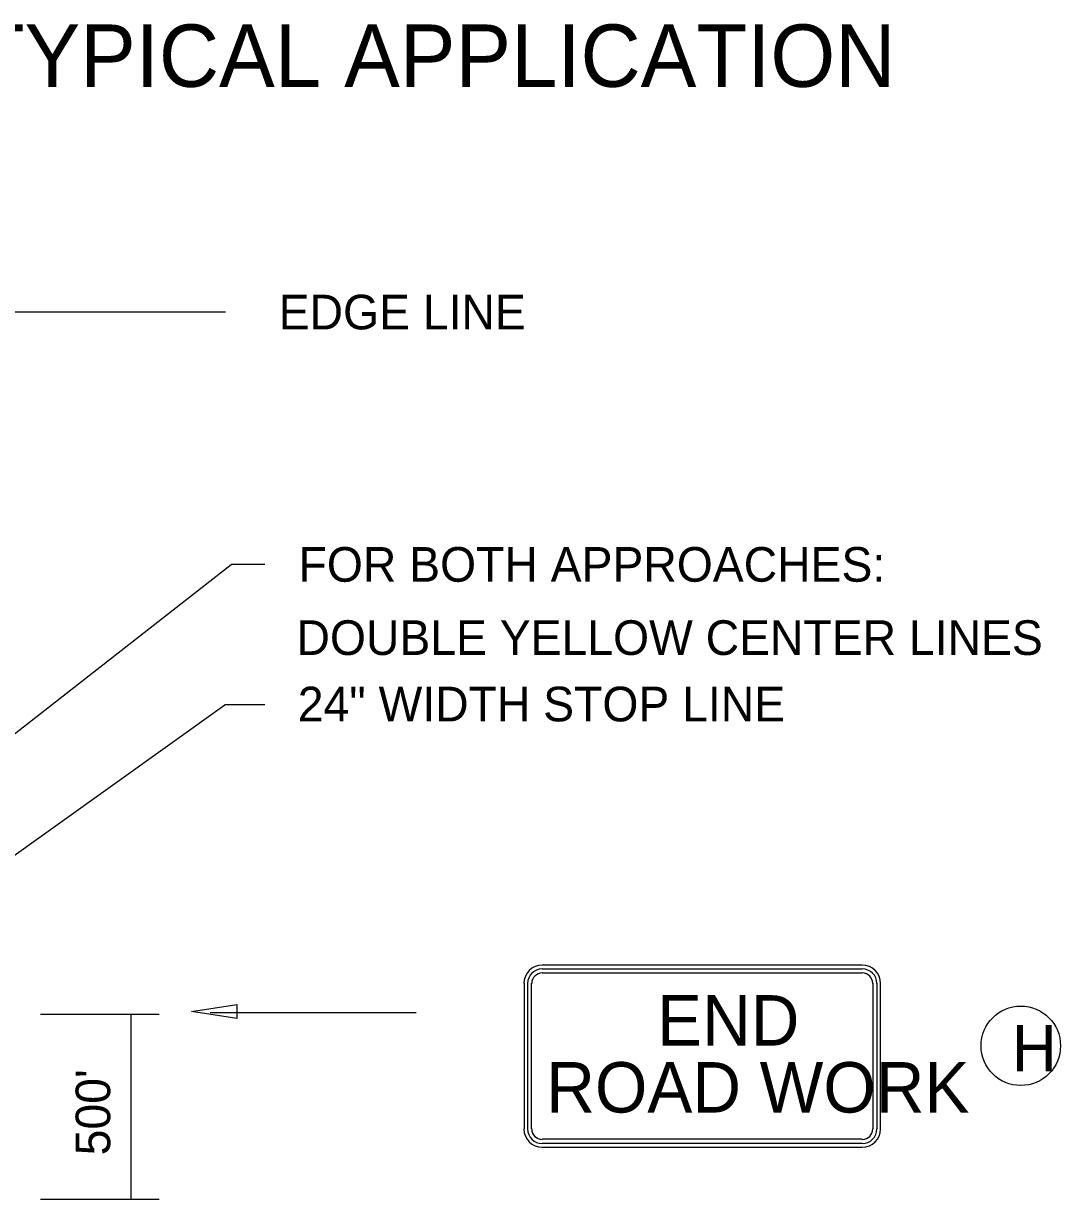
# Model space of a CAD drawing. Extents: x 1531.2 to 1538.6, y 1529.6 to 1539.7.
# Drawn here: x 1535.359 to 1537.155, y 1537.667 to 1539.704 of the extents above; entities that cross this region are included whole.
import ezdxf

# ---------------------------------------------------------------- set-up
doc = ezdxf.new("R2010")
doc.units = 0
for name, color, linetype in [('DETL-DIMS', 7, 'Continuous'), ('DETL-LINE', 7, 'Continuous'), ('DETL-NOTE', 7, 'Continuous'), ('DETL-TITL', 7, 'Continuous')]:
    doc.layers.add(name, color=color, linetype=linetype)

msp = doc.modelspace()

# ---------------------------------------------------------------- linework, layer by layer
at = {"layer": 'DETL-DIMS'}
for p, q in [((1535.1925, 1539.2044), (1535.7088, 1539.2044)), ((1534.7897, 1538.0412), (1535.7183, 1538.7668)), ((1535.777, 1538.7668), (1535.7183, 1538.7668)), ((1534.8078, 1537.8823), (1535.7074, 1538.5239)), ((1535.777, 1538.5239), (1535.7074, 1538.5239)), ((1535.5934, 1537.9872), (1535.3881, 1537.9872)), ((1535.5451, 1537.6671), (1535.5451, 1537.9872)), ((1535.6823, 1537.9909), (1536.0391, 1537.9909)), ((1535.5934, 1537.6671), (1535.3881, 1537.6671))]:
    msp.add_line(p, q, dxfattribs=at)
msp.add_lwpolyline([(1535.6495, 1537.9928), (1535.7281, 1538.0048), (1535.7281, 1537.9808)], close=True, dxfattribs=at)
at = {"layer": 'DETL-LINE'}
for p, q in [((1536.8119, 1538.0729), (1536.2572, 1538.0729)), ((1536.2572, 1538.0665), (1536.8119, 1538.0665)), ((1536.2572, 1538.0597), (1536.8119, 1538.0597)), ((1536.2259, 1538.0415), (1536.2259, 1537.7893)), ((1536.2323, 1537.7893), (1536.2323, 1538.0415)), ((1536.2389, 1537.7893), (1536.2389, 1538.0415)), ((1536.8299, 1538.0415), (1536.8299, 1537.7893)), ((1536.83, 1538.0413), (1536.8299, 1538.0415)), ((1536.8372, 1538.0415), (1536.8372, 1537.7893)), ((1536.8436, 1537.7893), (1536.8436, 1538.0415)), ((1536.8119, 1537.7713), (1536.2572, 1537.7713)), ((1536.8119, 1537.7641), (1536.2572, 1537.7641)), ((1536.2572, 1537.7577), (1536.8119, 1537.7577))]:
    msp.add_line(p, q, dxfattribs=at)
for centre, radius, start, end in [((1536.2573, 1538.0413), 0.0316, 90, 180), ((1536.2573, 1538.0413), 0.0252, 90, 180), ((1536.8119, 1538.0413), 0.0316, 0, 90), ((1536.8119, 1538.0413), 0.0252, 0, 90), ((1536.2573, 1538.0413), 0.0181, 90, 180), ((1536.8119, 1538.0413), 0.0181, 0, 90), ((1536.2573, 1537.7892), 0.0316, 180, 270), ((1536.2573, 1537.7892), 0.0252, 180, 270), ((1536.2573, 1537.7892), 0.0181, 180, 270), ((1536.8119, 1537.7892), 0.0316, 270, 0), ((1536.8119, 1537.7892), 0.0181, 270, 0), ((1536.8119, 1537.7892), 0.0252, 270, 0)]:
    msp.add_arc(centre, radius, start, end, dxfattribs=at)
at = {"layer": 'DETL-NOTE'}
msp.add_circle((1537.0865, 1537.9333), 0.0688, dxfattribs=at)

# ---------------------------------------------------------------- texts
at = {"layer": 'DETL-LINE'}
for s, p in [('END', (1536.4564, 1537.9337)), ('ROAD WORK', (1536.2644, 1537.8177))]:
    msp.add_text(s, height=0.08731, rotation=360, dxfattribs=at).set_placement(p)
at = {"layer": 'DETL-NOTE'}
for s, height, p in [('EDGE LINE', 0.06, (1535.8008, 1539.1739)), ('FOR BOTH APPROACHES:', 0.06, (1535.8352, 1538.7369)), ('DOUBLE YELLOW CENTER LINES', 0.06, (1535.8316, 1538.6101)), ('24" WIDTH STOP LINE', 0.06, (1535.8338, 1538.4951)), ('H', 0.08, (1537.0713, 1537.8891))]:
    msp.add_text(s, height=height, dxfattribs=at).set_placement(p)
msp.add_text("500'", height=0.06, rotation=90, dxfattribs=at).set_placement((1535.5089, 1537.7436))
at = {"layer": 'DETL-TITL'}
msp.add_text('TEMPORARY TRAFFIC CONTROL TYPICAL APPLICATION', height=0.108, dxfattribs=at).set_placement((1532.9213, 1539.5939))

doc.saveas('drawing.dxf')
